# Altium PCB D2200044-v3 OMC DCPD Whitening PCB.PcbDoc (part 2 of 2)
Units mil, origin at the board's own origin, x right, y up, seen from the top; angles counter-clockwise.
Board outline 7000 x 5000 mil, 4 copper layers (Top Layer, Layer 1 (+V), Layer 2 (-V), Bottom Layer), stack 19.156 mil thick; 95 components, 56 nets, 274 pads, 56 vias.
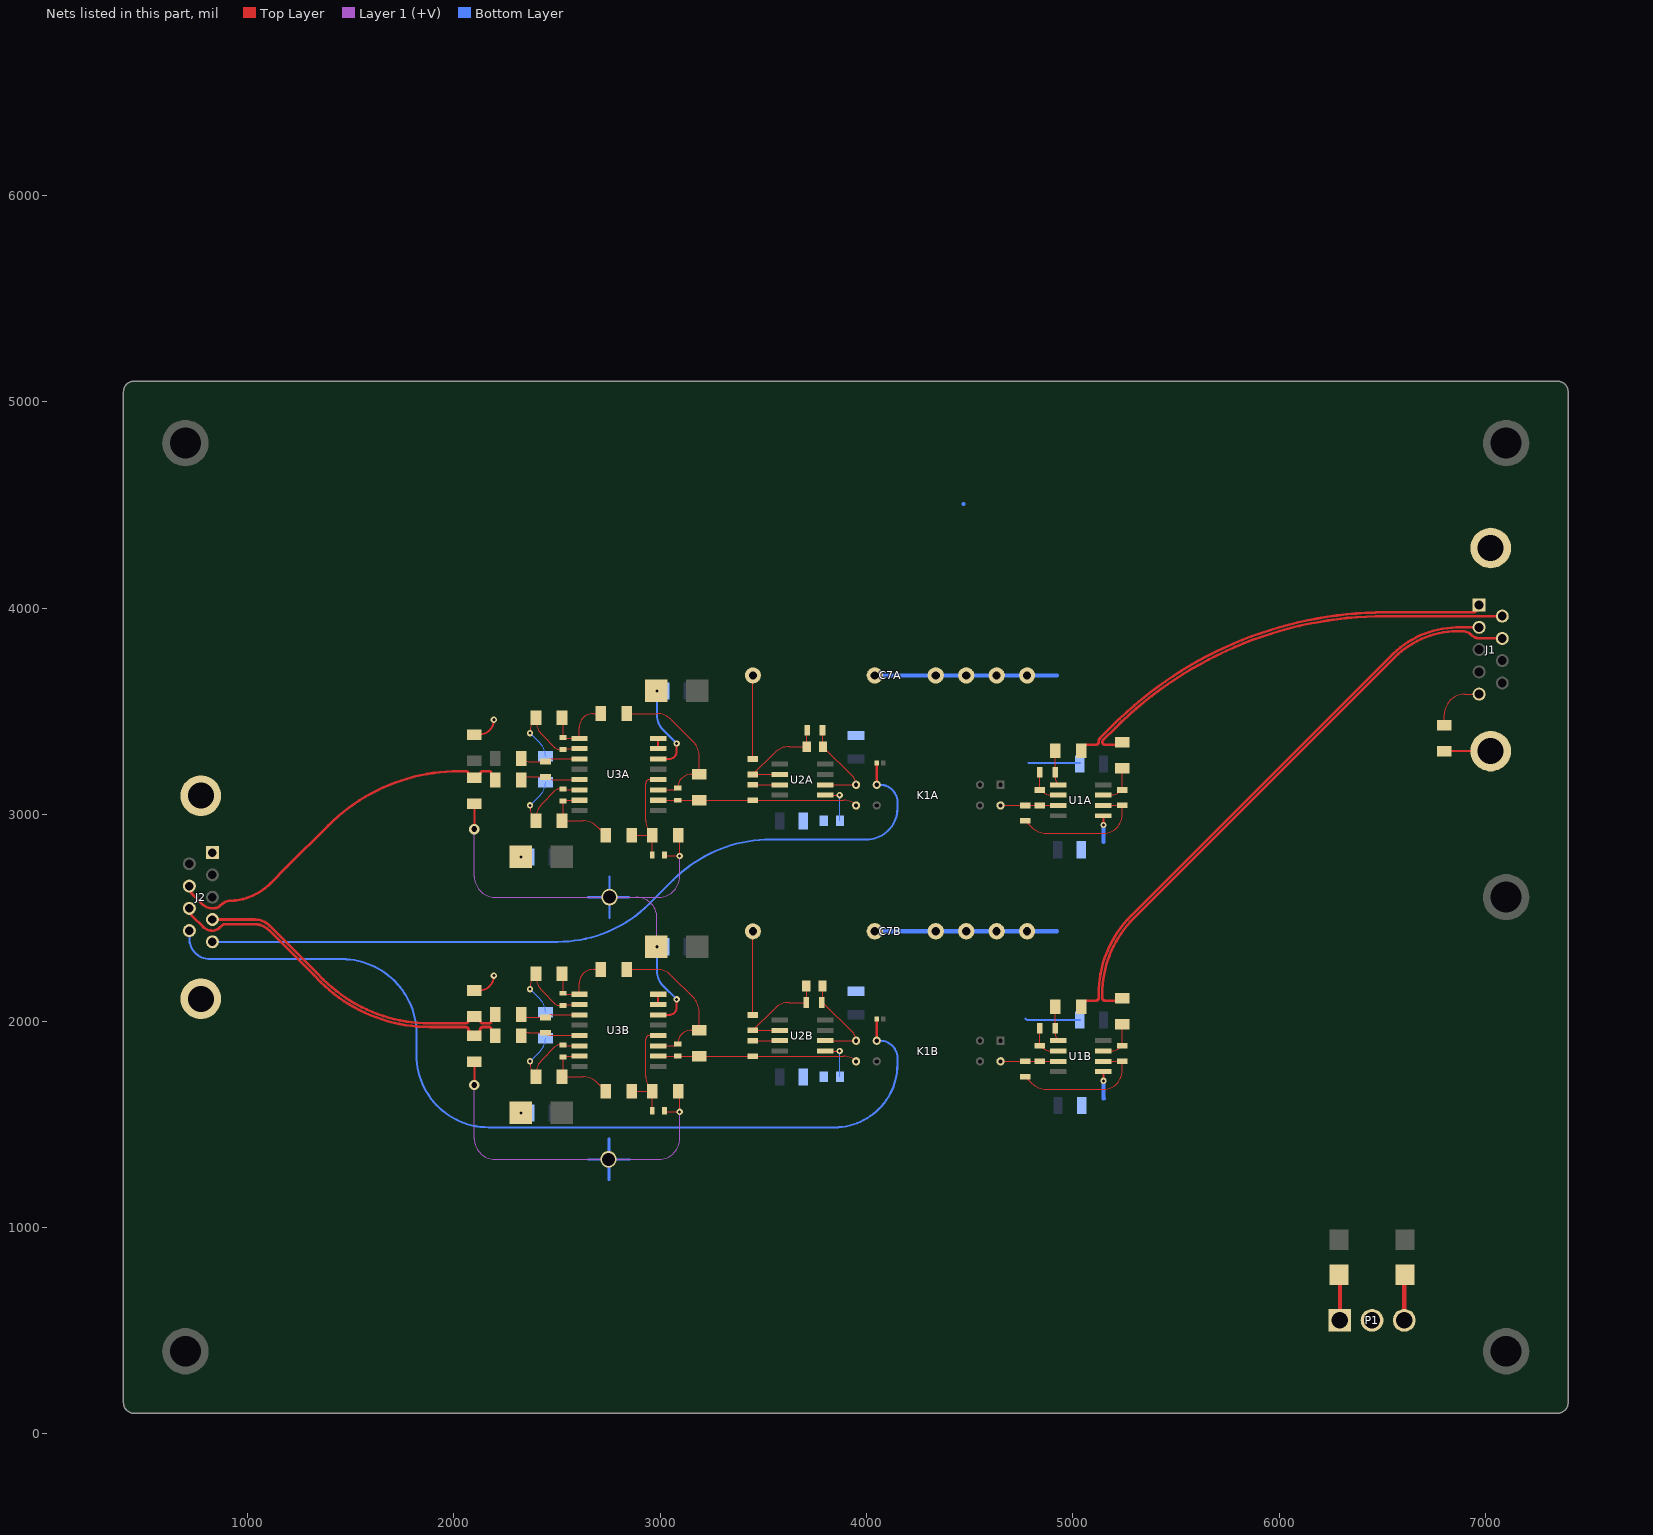
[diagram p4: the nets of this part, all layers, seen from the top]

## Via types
v1: diameter 31, hole 15, Top Layer to Bottom Layer, tented both sides, 52 vias
v2: diameter 50, hole 28, Top Layer to Bottom Layer, 2 vias
v3: diameter 31, hole 15, Top Layer to Bottom Layer, 2 vias

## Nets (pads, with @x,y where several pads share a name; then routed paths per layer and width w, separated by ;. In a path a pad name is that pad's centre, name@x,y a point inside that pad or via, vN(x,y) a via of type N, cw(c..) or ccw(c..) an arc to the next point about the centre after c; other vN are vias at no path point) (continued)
"DCPD In A_p": J2.7 R11A.1 R15A.1 | length 1833.9
  Top Layer w12.64: J2.7@719,2654 ccw(c779.36,2654) 736.68,2611.32 781.49,2566.51 ccw(c831,2616.01) 831,2546 834.79,2546 ccw(c834.79,2597.21) 870.99,2560.99 873.91,2563.91 cw(c920,2517.82) 910.17,2582.25 cw(c911.97,2569.74) 911.77,2582.38 ccw(c908.08,2870.33) 928.78,2583.1 ; 950.08,2585.44 cw(c908.08,2870.33) 928.79,2583.1 ; R15A.1@2202.01,3168 2188.57,3181.43 cw(c2202.66,3195.52) 2182.74,3195.52 2182.74,3198.54 ccw(c2170.1,3198.54) 2179.04,3207.48 ccw(c2170.1,3198.54) 2170.1,3211.18 2141.75,3211.18 ccw(c2141.75,3198.54) 2132.81,3207.48 2131.41,3206.07 ccw(c2136.97,3200.52) 2129.11,3200.52 cw(c2121.25,3200.52) 2126.81,3194.96 2116.8,3184.95 cw(c2100,3201.75) R11A.1@2100,3177.99 cw(c2100,3201.75) 2083.2,3184.95 2073.19,3194.96 cw(c2078.75,3200.52) 2070.89,3200.52 ccw(c2063.03,3200.52) 2068.59,3206.08 ccw(c2056.27,3193.76) 2056.27,3211.18 2028.84,3211.18 ccw(c2028.84,2311.49) 1392.95,2947.95 1193.45,2748.45 1111.68,2666.68 cw(c908.08,2870.33) 928.78,2583.1
"DCPD In B_n": J2.4 R17B.1 R21B.2 | length 1599.8
  Top Layer w12.64: J2.4@831,2492 1036.53,2492 cw(c1036.53,2392) 1107.24,2462.71 1335.35,2234.6 ; 1335.39,2234.56 1367.52,2202.43 1367.64,2202.31 ccw(c1883.57,2718.99) 1883.19,1988.82 2056.27,1988.82 ccw(c2056.27,2006.24) 2068.59,1993.92 ccw(c2063.03,1999.48) 2070.89,1999.48 cw(c2078.75,1999.48) 2073.19,2005.04 2083.2,2015.05 cw(c2100,1998.25) R21B.2@2100,2022.01 cw(c2100,1998.25) 2116.8,2015.05 2126.81,2005.04 cw(c2121.25,1999.48) 2129.11,1999.48 ccw(c2136.97,1999.48) 2131.41,1993.92 2132.81,1992.52 ccw(c2141.75,2001.46) 2141.75,1988.82 2170.1,1988.82 ccw(c2170.1,2001.46) 2179.04,1992.52 ccw(c2170.1,2001.46) 2182.74,2001.46 2182.74,2004.48 cw(c2202.66,2004.48) 2188.57,2018.57 R17B.1@2202.01,2032
"DCPD In B_p": J2.8 R11B.1 R15B.1 | length 1771.8
  Top Layer w12.64: J2.8@719,2546 ccw(c775.09,2546) 735.43,2506.34 784.51,2457.26 ccw(c831,2503.75) 831,2438 ccw(c831,2487.82) 866.23,2452.59 873.91,2460.27 cw(c896.74,2437.44) 896.74,2469.73 1033.85,2469.73 cw(c1033.85,2369.73) 1104.56,2440.44 1322.82,2222.18 1322.91,2222.09 1354.72,2190.28 ; 1354.73,2190.27 ccw(c1883.57,2718.99) 1883.24,1971.18 1883.69,1971.18 2056.27,1971.18 cw(c2056.27,1953.76) 2068.59,1966.08 cw(c2063.03,1960.52) 2070.89,1960.52 ccw(c2078.75,1960.52) 2073.19,1954.96 2083.2,1944.95 ccw(c2100,1961.75) 2100,1937.99 ccw(c2100,1961.75) 2116.8,1944.95 2126.81,1954.96 ccw(c2121.25,1960.52) 2129.11,1960.52 cw(c2136.97,1960.52) 2131.41,1966.07 2132.81,1967.48 cw(c2141.75,1958.54) 2141.75,1971.18 2170.1,1971.18 cw(c2170.1,1958.54) 2179.04,1967.48 cw(c2170.1,1958.54) 2182.74,1958.54 2182.74,1955.52 ccw(c2202.66,1955.52) 2188.57,1941.43 R15B.1@2202.01,1928
GND: C1A.2 C1B.2 C2A.2 C2B.2 C3A.2 C3B.2 C4A.2 C4B.2 C5A.2 C5B.2 C7A.2 C7B.2 C9A.2 C9B.2 C12A.2 C12B.2 C14A.2 C14B.2 C15A.2 C15B.2 C16A.1 C16B.1 J1.10 J1.11 J2.1 J2.10 J2.11 P1.2 R1.1 R11A.2 R11B.2 R14A.2 R14B.2 R21A.1 R21B.1 TP1A.1 TP1B.1 U1A.5 U1B.5 U3A.14 U3B.14 | length 8999.4
  Top Layer w6: C9B.2@3021.06,1565 3026.06,1560 3085,1560 v1@3090,1565 ; C9A.2@3021.06,2805 3026.06,2800 v1@3085,2800 ; R14B.2@3087.99,1660 3095,1652.99 3095,1570 v1@3090,1565 ; R14A.2@3087.99,2900 3095,2892.99 v1@3095,2810 ; v1(3095,1560) v1@3090,1565
  Top Layer w10: v2(2100,1690) R11B.2@2100,1802.02 ; R21B.1@2100,2147.99 2122.99,2147.99 ccw(c2122.99,2220) v1(2195,2220) ; v2(2100,2930) R11A.2@2100,3052.01 ; R21A.1@2100,3387.99 2122.99,3387.99 ccw(c2122.99,3460) v1(2195,3460) ; U3B.14@2990.94,2030 3045,2030 ccw(c3045,2065) 3080,2065 v1(3080,2105) ; U3A.14@2990.94,3270 3045,3270 ccw(c3045,3305) 3080,3305 v1(3080,3345) ; v1(5148.58,1710) U1B.5@5148.58,1754.8 ; v1(5148.58,2950) U1A.5@5148.58,2994.8 ; R1.1@6800,3308 J1.10@7025,3308
  Layer 1 (+V) w6: v2(2100,1690) 2100,1430 ccw(c2200,1430) 2200,1330 2995,1330 ccw(c2995,1430) 3095,1430 v1(3095,1560) ; v2(2100,2930) 2100,2700 ccw(c2200,2700) 2200,2600 2885,2600 ; v1(2985,2360) 2985,2500 ccw(c2885,2500) 2885,2600 ; v1(3095,2800) 3095,2700 cw(c2995,2700) 2995,2600 2885,2600
  Bottom Layer w10: 2650,1330 TP1B.1@2750,1330 ; 2650,2600 2850,2600 ; 2655,1330 TP1B.1@2755,1330 ; 2750,1230 TP1B.1@2750,1330 ; 2750,1430 TP1B.1@2750,1330 ; 2755,1230 TP1B.1@2755,1330 ; 2755,1430 TP1B.1@2755,1330 ; 2755,2500 TP1A.1@2755,2600 2755,2700 ; 2850,1330 TP1B.1@2750,1330 ; 2855,1330 TP1B.1@2755,1330 ; C15B.2@3022.91,2360 v1(2985,2360) 2985,2241.42 ccw(c3085,2241.42) 3014.29,2170.71 v1(3080,2105) ; C15A.2@3022.91,3600 v1(2985,3600) 2985,3481.42 ccw(c3085,3481.42) 3014.29,3410.71 v1(3080,3345) ; 4770,2011.2 ccw(c4784.97,2026.17) 4784.97,2005 C1B.2@5034.41,2005 ; 4784.97,3250 C1A.2@5034.41,3250
  Bottom Layer w20: C7B.2@4040.55,2435 4924,2435 ; C7A.2@4040.55,3675 C7A.2@4335.83,3675 C7A.2@4483.46,3675 C7A.2@4631.1,3675 C7A.2@4778.74,3675 4924,3675 ; 4470.2,4505 4471,4505 ; v1(5148.58,1710) 5148.58,1628.42 ccw(c5153.42,1628.42) 5150,1625 ; 5148.58,2868.42 v1(5148.58,2950)
  other v1: 2325.49,1555 2325.49,2795
NetC4A_1: C4A.1 U2A.5 | length 195
  Top Layer w5: U2A.5@3800,3094.8 v1(3870,3094.8)
  Bottom Layer w5: C4A.1@3870,2969.8 v1(3870,3094.8)
NetC4B_1: C4B.1 U2B.5 | length 195
  Top Layer w5: U2B.5@3800,1854.8 v1(3870,1854.8)
  Bottom Layer w5: C4B.1@3870,1729.8 v1(3870,1854.8)
NetC6A_1: C6A.1 R9A.1 R10A.2 U2A.2 | length 522.8
  Top Layer w5: U2A.2@3580,3194.8 R10A.2@3450,3194.8 3555.71,3300.51 cw(c3626.42,3229.8) 3626.42,3329.8 R9A.1@3710.63,3329.8 3710.63,3405.05 cw(c3717.35,3405.05) C6A.1@3712.6,3409.8
NetC6A_2: C6A.2 K1A.4 R9A.2 U2A.6 | length 479.5
  Top Layer w5: C6A.2@3787.4,3409.8 cw(c3782.65,3405.05) 3789.37,3405.05 R9A.2@3789.37,3329.8 3932.77,3186.41 cw(c3891.17,3144.8) K1A.4@3950,3144.8 U2A.6@3800,3144.8
NetC6B_1: C6B.1 R9B.1 R10B.2 U2B.2 | length 522.8
  Top Layer w5: U2B.2@3580,1954.8 R10B.2@3450,1954.8 3555.71,2060.51 cw(c3626.42,1989.8) 3626.42,2089.8 3710.63,2089.8 3710.63,2165.05 cw(c3717.35,2165.05) R9B.1@3712.6,2169.8
NetC6B_2: C6B.2 K1B.4 R9B.2 U2B.6 | length 479.5
  Top Layer w5: R9B.2@3787.4,2169.8 cw(c3782.65,2165.05) 3789.37,2165.05 3789.37,2089.8 3932.77,1946.41 cw(c3891.17,1904.8) K1B.4@3950,1904.8 U2B.6@3800,1904.8
NetC7A_1: C7A.1 R10A.1 | length 401.5
  Top Layer w5: R10A.1@3450,3273.54 C7A.1@3450,3675
NetC7B_1: C7B.1 R10B.1 | length 401.5
  Top Layer w5: R10B.1@3450,2033.54 C7B.1@3450,2435
NetC8A_1: C8A.1 R12A.1 R16A.2 U3A.6 | length 523.2
  Top Layer w6: v1(2370,3045) 2370,3040.05 ccw(c2469.07,3040.05) R12A.1@2399.02,2970 2399.02,2982.59 cw(c2499.02,2982.59) 2428.31,3053.31 2490,3115 cw(c2513,3092) 2513,3124.53 C8A.1@2530,3124.53 ccw(c2540.93,3135.46) 2540.93,3120 U3A.6@2609.06,3120
  Bottom Layer w6: v1(2370,3045) 2418.83,3093.83 ccw(c2355.66,3157.01) R16A.2@2445,3157.01
NetC8A_2: C8A.2 R12A.2 R13A.1 U3A.7 | length 413.8
  Top Layer w6: U3A.7@2609.06,3070 2540.93,3070 ccw(c2540.93,3054.54) C8A.2@2530,3065.47 2530,2982.07 cw(c2512.93,2982.07) R12A.2@2525,2970 2625.59,2970 cw(c2625.59,2870) 2696.3,2940.71 R13A.1@2737.01,2900
NetC8B_1: C8B.1 R12B.1 R16B.2 U3B.6 | length 523.2
  Top Layer w6: v1(2370,1805) 2370,1800.05 ccw(c2469.07,1800.05) R12B.1@2399.02,1730 2399.02,1742.59 cw(c2499.02,1742.59) 2428.31,1813.31 2490,1875 cw(c2513,1852) 2513,1884.53 C8B.1@2530,1884.53 ccw(c2540.93,1895.46) 2540.93,1880 U3B.6@2609.06,1880
  Bottom Layer w6: v1(2370,1805) 2418.83,1853.83 ccw(c2355.66,1917.01) R16B.2@2445,1917.01
NetC8B_2: C8B.2 R12B.2 R13B.1 U3B.7 | length 413.8
  Top Layer w6: U3B.7@2609.06,1830 2540.93,1830 ccw(c2540.93,1814.54) C8B.2@2530,1825.47 2530,1742.07 cw(c2512.93,1742.07) R12B.2@2525,1730 2625.59,1730 cw(c2625.59,1630) 2696.3,1700.71 R13B.1@2737.01,1660
NetC9A_1: C9A.1 R13A.2 R14A.1 U3A.12 | length 525.7
  Top Layer w6: R13A.2@2862.99,2900 R14A.1@2962.01,2900 ; C9A.1@2962.01,2805 R14A.1@2962.01,2900 ; U3A.12@2990.94,3170 2949.08,3170 ccw(c2949.08,3150.92) 2930,3150.92 2930,2973.43 ccw(c3030,2973.43) 2959.29,2902.72 R14A.1@2962.01,2900
NetC9B_1: C9B.1 R13B.2 R14B.1 U3B.12 | length 525.7
  Top Layer w6: R13B.2@2862.99,1660 R14B.1@2962.01,1660 ; C9B.1@2962.01,1565 R14B.1@2962.01,1660 ; U3B.12@2990.94,1930 2949.08,1930 ccw(c2949.08,1910.92) 2930,1910.92 2930,1733.43 ccw(c3030,1733.43) 2959.29,1662.72 R14B.1@2962.01,1660
NetC10A_1: C10A.1 R16A.1 R18A.1 U3A.2 | length 523.2
  Top Layer w5: v1(2370,3395) 2370,3399.95 cw(c2469.07,3399.95) R18A.1@2399.02,3470
  Top Layer w6: R18A.1@2399.02,3470 2399.02,3457.41 ccw(c2499.02,3457.41) 2428.31,3386.69 2490,3325 ccw(c2513,3348) 2513,3315.47 C10A.1@2530,3315.47 cw(c2540.93,3304.54) 2540.93,3320 U3A.2@2609.06,3320
  Bottom Layer w5: v1(2370,3395) 2418.83,3346.17 cw(c2355.66,3282.99) R16A.1@2445,3282.99
NetC10A_2: C10A.2 R18A.2 R19A.1 U3A.1 | length 396.3
  Top Layer w6: R18A.2@2525,3470 cw(c2512.93,3457.93) 2530,3457.93 C10A.2@2530,3374.53 ccw(c2540.93,3385.46) 2540.93,3370 U3A.1@2609.06,3370 2609.06,3423.13 cw(c2675.92,3423.13) 2675.92,3490 R19A.1@2737.01,3490
NetC10B_1: C10B.1 R16B.1 R18B.1 U3B.2 | length 523.2
  Top Layer w5: v1(2370,2155) 2370,2159.95 cw(c2469.07,2159.95) R18B.1@2399.02,2230
  Top Layer w6: R18B.1@2399.02,2230 2399.02,2217.41 ccw(c2499.02,2217.41) 2428.31,2146.69 2490,2085 ccw(c2513,2108) 2513,2075.47 C10B.1@2530,2075.47 cw(c2540.93,2064.54) 2540.93,2080 U3B.2@2609.06,2080
  Bottom Layer w5: v1(2370,2155) 2418.83,2106.17 cw(c2355.66,2042.99) R16B.1@2445,2042.99
NetC10B_2: C10B.2 R18B.2 R19B.1 U3B.1 | length 396.3
  Top Layer w6: R18B.2@2525,2230 cw(c2512.93,2217.93) 2530,2217.93 C10B.2@2530,2134.53 ccw(c2540.93,2145.46) 2540.93,2130 U3B.1@2609.06,2130 2609.06,2183.13 cw(c2675.92,2183.13) 2675.92,2250 R19B.1@2737.01,2250
NetC11A_1: C11A.1 R17A.2 U3A.3 | length 288.3
  Top Layer w6: R17A.2@2327.99,3272 ccw(c2363.24,3307.24) 2363.24,3257.4 C11A.1@2445,3257.4 cw(c2475.42,3226.99) 2475.42,3270 U3A.3@2609.06,3270
NetC11A_2: C11A.2 R15A.2 U3A.5 | length 288.3
  Top Layer w6: R15A.2@2327.99,3168 cw(c2363.24,3132.76) 2363.24,3182.6 C11A.2@2445,3182.6 ccw(c2475.42,3213.01) 2475.42,3170 U3A.5@2609.06,3170
NetC11B_1: C11B.1 R17B.2 U3B.3 | length 288.3
  Top Layer w6: R17B.2@2327.99,2032 ccw(c2363.24,2067.24) 2363.24,2017.4 C11B.1@2445,2017.4 cw(c2475.42,1986.99) 2475.42,2030 U3B.3@2609.06,2030
NetC11B_2: C11B.2 R15B.2 U3B.5 | length 288.3
  Top Layer w6: R15B.2@2327.99,1928 cw(c2363.24,1892.76) 2363.24,1942.6 C11B.2@2445,1942.6 ccw(c2475.42,1973.01) 2475.42,1930 U3B.5@2609.06,1930
NetC13A_1: C13A.1 R19A.2 R20A.1 U3A.11 | length 755.4
  Top Layer w6: R19A.2@2862.99,3490 2983.58,3490 cw(c2983.58,3390) 3054.29,3460.71 3160.71,3354.29 cw(c3090,3283.58) 3190,3283.58 R20A.1@3190,3195.98 3151.93,3195.98 ccw(c3151.93,3129.06) C13A.1@3085,3129.06 cw(c3063.14,3150.92) 3063.14,3120 U3A.11@2990.94,3120
NetC13A_2: C13A.2 K1A.5 R8A.1 R20A.2 U3A.10 | length 965.8
  Top Layer w5: U3A.10@2990.94,3070 C13A.2@3085,3070 R20A.2@3190,3070 R8A.1@3450,3070 3889.17,3070 cw(c3889.17,2983.97) K1A.5@3950,3044.8
NetC13B_1: C13B.1 R19B.2 R20B.1 U3B.11 | length 755.4
  Top Layer w6: R19B.2@2862.99,2250 2983.58,2250 cw(c2983.58,2150) 3054.29,2220.71 3160.71,2114.29 cw(c3090,2043.58) 3190,2043.58 R20B.1@3190,1955.98 3151.93,1955.98 ccw(c3151.93,1889.06) C13B.1@3085,1889.06 cw(c3063.14,1910.92) 3063.14,1880 U3B.11@2990.94,1880
NetC13B_2: C13B.2 K1B.5 R8B.1 R20B.2 U3B.10 | length 989.2
  Top Layer w5: R20B.2@3190,1830 R8B.1@3450,1830 3889.17,1830 cw(c3889.17,1743.97) K1B.5@3950,1804.8
  Top Layer w6: U3B.10@2990.94,1830 C13B.2@3085,1830 R20B.2@3190,1830 R20B.2@3189.76,1816.44 ; R20B.2@3189.75,1816.4 ccw(c3195.75,1816.33) 3189.75,1816.33 3189.76,1813.91 3191.43,1812.17 ccw(c3195.75,1816.33) 3191.6,1812 3193.27,1810.4 R20B.2@3195.58,1810.33
NetD1_1: D1.1 P1.1 | length 221.4
  Top Layer w20: D1.1@6290,770.35 cw(c6280.34,760.7) 6294,760.7 P1.1@6294,550
NetD2_2: D2.2 P1.3 | length 221.4
  Top Layer w20: P1.3@6606,550 6606,760.7 cw(c6619.66,760.7) D2.2@6610,770.35
NetJ1_5: J1.5 R1.2 | length 276.1
  Top Layer w6: R1.2@6800,3433.98 6800,3484 cw(c6900,3484) 6900,3584 J1.5@6969,3584
NetK1A_8: K1A.8 R3A.1 R6A.1 U1A.3 | length 278.6
  Top Layer w5: K1A.8@4650,3044.8 R6A.1@4770,3044.8 R3A.1@4840,3044.8 U1A.3@4928.58,3044.8
NetK1B_8: K1B.8 R3B.1 R6B.1 U1B.3 | length 278.6
  Top Layer w5: K1B.8@4650,1804.8 R6B.1@4770,1804.8 R3B.1@4840,1804.8 U1B.3@4928.58,1804.8
NetR2A_1: R2A.1 R3A.2 U1A.2 | length 180.6
  Top Layer w5: R2A.1@4840,3205 R3A.2@4840,3119.61 ccw(c4899.88,3179.49) 4899.88,3094.8 U1A.2@4928.58,3094.8
NetR2A_2: R2A.2 R4A.1 U1A.1 | length 169
  Top Layer w5: R4A.1@4915,3310 4915,3205.2 R2A.2@4914.8,3205 4914.8,3178.07 ccw(c4961.85,3178.07) U1A.1@4928.58,3144.8
NetR2B_1: R2B.1 R3B.2 U1B.2 | length 180.6
  Top Layer w5: R2B.1@4840,1965 R3B.2@4840,1879.61 ccw(c4899.88,1939.49) 4899.88,1854.8 U1B.2@4928.58,1854.8
NetR2B_2: R2B.2 R4B.1 U1B.1 | length 169
  Top Layer w5: R4B.1@4915,2070 4915,1965.2 R2B.2@4914.8,1965 4914.8,1938.07 ccw(c4961.85,1938.07) U1B.1@4928.58,1904.8
NetR5A_1: R5A.1 R6A.2 U1A.6 | length 677.8
  Top Layer w5: R6A.2@4770,2970 4800.71,2939.29 ccw(c4871.42,3010) 4871.42,2910 5148.58,2910 ccw(c5148.58,3001.42) 5240,3001.42 R5A.1@5240,3045 U1A.6@5148.78,3045
  Top Layer w10: U1A.6@5148.58,3044.8 U1A.6@5148.78,3045
NetR5A_2: R5A.2 R7A.1 U1A.7 | length 202.9
  Top Layer w5: U1A.7@5148.58,3094.8 5179.64,3094.8 ccw(c5179.64,3180.16) R5A.2@5240,3119.8 ; R5A.2@5240.2,3120 R7A.1@5240.2,3224.8
NetR5B_1: R5B.1 R6B.2 U1B.6 | length 677.8
  Top Layer w5: R6B.2@4770,1730 4800.71,1699.29 ccw(c4871.42,1770) 4871.42,1670 5148.58,1670 ccw(c5148.58,1761.42) 5240,1761.42 R5B.1@5240,1805 U1B.6@5148.78,1805
  Top Layer w10: U1B.6@5148.58,1804.8 U1B.6@5148.78,1805
NetR5B_2: R5B.2 R7B.1 U1B.7 | length 202.9
  Top Layer w5: U1B.7@5148.58,1854.8 5179.64,1854.8 ccw(c5179.64,1940.16) R5B.2@5240,1879.8 ; R5B.2@5240.2,1880 R7B.1@5240.2,1984.8
NetR8A_2: R8A.2 U2A.3 | length 130
  Top Layer w5: R8A.2@3450,3144.8 U2A.3@3580,3144.8
NetR8B_2: R8B.2 U2B.3 | length 130
  Top Layer w5: R8B.2@3450,1904.8 U2B.3@3580,1904.8
NetU3A_15: U3A.15 U3A.16 | length 50
  Top Layer w10: U3A.15@2990.94,3320 U3A.16@2990.94,3370
NetU3B_15: U3B.15 U3B.16 | length 50
  Top Layer w10: U3B.15@2990.94,2080 U3B.16@2990.94,2130
"OMC A - DCPD A_n": J1.6 R7A.2 | length 2221.6
  Top Layer w12.64: R7A.2@5240.2,3350.79 cw(c5212.01,3378.97) 5212.01,3339.11 5155.56,3339.11 cw(c5155.56,3351.75) 5146.62,3342.81 cw(c5155.56,3351.75) 5142.92,3351.75 cw(c5155.56,3351.75) 5146.61,3360.69 5205.88,3419.95 cw(c6515.19,2110.83) 6515.19,3962.34 6515.26,3962.34 6559.45,3962.34 6559.79,3962 J1.6@7081,3962
"OMC A - DCPD A_p": J1.1 R4A.2 | length 2157.3
  Top Layer w12.64: R4A.2@5040.98,3310 cw(c5064.75,3310) 5047.94,3326.8 5050.62,3329.48 cw(c5073.88,3306.22) 5073.88,3339.11 5112.63,3339.11 ccw(c5112.63,3351.75) 5121.57,3342.81 ccw(c5112.63,3351.75) 5125.28,3351.75 5125.28,3355.41 cw(c5146.74,3355.41) 5131.56,3370.58 5193.4,3432.43 cw(c6515.19,2110.83) 6515.19,3979.98 6558.77,3979.98 6559.11,3980.32 6933.32,3980.32 ccw(c6933.32,4016) J1.1@6969,4016
"OMC A - DCPD B_n": J1.7 R7B.2 | length 2887.3
  Top Layer w12.64: R7B.2@5240.2,2110.79 cw(c5212.01,2138.97) 5212.01,2099.11 5155.56,2099.11 cw(c5155.56,2111.75) 5146.62,2102.81 cw(c5155.56,2111.75) 5142.92,2111.75 5142.92,2131.79 cw(c5659.9,2131.47) 5294.26,2496.95 6559.74,3762.43 cw(c6865.74,3455.84) 6863.33,3889 6888.96,3889 cw(c6888.96,3830.96) 6930,3872 ccw(c6973.46,3915.46) 6973.46,3854 J1.7@7081,3854
"OMC A - DCPD B_p": J1.2 R4B.2 | length 2792.9
  Top Layer w12.64: R4B.2@5040.98,2070 cw(c5064.75,2070) 5047.94,2086.8 cw(c5077.66,2057.08) 5077.66,2099.11 5112.63,2099.11 ccw(c5112.63,2111.75) 5121.57,2102.81 ccw(c5112.63,2111.75) 5125.28,2111.75 5125.28,2131.39 5125.28,2131.74 cw(c5659.9,2131.47) 5281.93,2509.57 6468.18,3695.82 6546.89,3774.54 cw(c6867.17,3454.68) 6552.45,3780.01 6553.65,3781.16 cw(c6867.36,3454.22) 6858.33,3907.23 6860,3907.26 6967.22,3907.26 ccw(c6967.22,3909.78) J1.2@6969,3908
Whitening-A: D3A.1 J2.5 K1A.3 | length 3838.6
  Top Layer w10: K1A.3@4050,3144.8 D3A.1@4050,3249.8
  Bottom Layer w10: J2.5@831,2384 2504.04,2384 ccw(c2504.09,3011.47) 2947.82,2567.82 3064.59,2684.59 cw(c3536.31,2212.94) 3536.31,2880 4000.24,2880 ccw(c4000.24,3029.76) 4150,3029.76 4150,3061.69 ccw(c4066.88,3061.69) 4066.88,3144.8 K1A.3@4050,3144.8
Whitening-B: D3B.1 J2.9 K1B.3 | length 4494.3
  Top Layer w10: K1B.3@4050,1904.8 D3B.1@4050,2009.8
  Bottom Layer w10: J2.9@719,2438 719,2400 ccw(c819,2400) 819,2300 1457.97,2300 cw(c1457.97,1937.97) 1820,1937.97 1820,1833.84 ccw(c2168.84,1833.84) 2168.84,1485 3000.1,1485 ; 3000.15,1485 3845.24,1485 ccw(c3845.24,1789.76) 4150,1789.76 4150,1821.69 ccw(c4066.88,1821.69) 4066.88,1904.8 K1B.3@4050,1904.8
pads on no net: J1.3 J1.4 J1.8 J1.9 J2.2 J2.6 K1A.2 K1A.6 K1A.7 K1B.2 K1B.6 K1B.7 MH1.1 MH2.1 MH3.1 MH4.1 MH5.1 U2A.1 U2A.8 U2B.1 U2B.8 U3A.8 U3A.9 U3B.8 U3B.9

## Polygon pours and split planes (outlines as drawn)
no net on Top Overlay "NONET_L-01_P-001" (solid): 5640,230 5640,1480 6015,1480 6015,230
+15 on Layer 1 (+V) "+15_L02_P000" (solid, remove dead copper, pour order 0): 450,5000 cw(c500,5000) 500,5050 7300,5050 cw(c7300.01,5000.01) 7350,5000 7350,200 cw(c7300.02,199.98) 7300,150 500,150 cw(c499.99,199.99) 450,200
-15 on Layer 2 (-V) "-15_L03_P001" (solid, remove dead copper, pour order 1): 450,5000 cw(c500,5000) 500,5050 7300,5050 cw(c7300.01,5000.01) 7350,5000 7350,200 cw(c7307.42,192.58) 7300,150 500,150 cw(c499.99,199.99) 450,200
GND on Bottom Layer "GND_L04_P002" (solid, remove dead copper, pour order 2): 450,5000 cw(c500,5000) 500,5050 7300,5050 cw(c7300.01,5000.01) 7350,5000 7350,200 cw(c7300.01,199.99) 7300,150 500,150 cw(c499.99,199.99) 450,200

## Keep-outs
Top Layer:
  lines w10: 6165,1310 cw(c6215,1310) 6215,1360 6365,1360 ; 6165,1310 ccw(c6165,1310) 6165,1310 ; 6165,1310 6165,1160 ccw(c6215,1160) 6215,1110 ; 6215,1110 ccw(c6215,1110) 6215,1110 ; 6215,1110 6365,1110 ccw(c6365,1160) 6415,1160 6415,1310 ccw(c6365,1310) 6365,1360 ; 6365,1360 ccw(c6365,1360) 6365,1360 ; 6365,1360 6365,1360 ; 6487,1310 cw(c6537,1310) 6537,1360 6687,1360 ; 6487,1310 ccw(c6487,1310) 6487,1310 ; 6487,1310 6487,1160 ccw(c6537,1160) 6537,1110 ; 6537,1110 ccw(c6537,1110) 6537,1110 ; 6537,1110 6687,1110 ccw(c6687,1160) 6737,1160 6737,1310 ccw(c6687,1310) 6687,1360 ; 6687,1360 ccw(c6687,1360) 6687,1360
Layer 1 (+V):
  lines w10: 6485,1160 ccw(c6535,1160) 6535,1110 6685,1110 ccw(c6685,1160) 6735,1160 6735,1310 ccw(c6685,1310) 6685,1360 6535,1360 ccw(c6535,1310) 6485,1310 6485,1160
Layer 2 (-V):
  lines w10: 6165,1160 ccw(c6215,1160) 6215,1110 6365,1110 ccw(c6365,1160) 6415,1160 6415,1310 ccw(c6365,1310) 6365,1360 6215,1360 ccw(c6215,1310) 6165,1310 6165,1160
Bottom Layer:
  lines w10: 6165,1160 ccw(c6215,1160) 6215,1110 6365,1110 ccw(c6365,1160) 6415,1160 6415,1310 ccw(c6365,1310) 6365,1360 6215,1360 ccw(c6215,1310) 6165,1310 6165,1160 ; 6485,1160 ccw(c6535,1160) 6535,1110 6685,1110 ccw(c6685,1160) 6735,1160 6735,1310 ccw(c6685,1310) 6685,1360 6535,1360 ccw(c6535,1310) 6485,1310 6485,1160
  lines w25: 4040.55,2435 4846.06,2435 ; 4040.55,3675 4846.06,3675
Keep-Out Layer:
  circle w10: c4040.55,2435 r50
  circle w10: c4335.83,2435 r50
  circle w10: c4483.46,2435 r50
  circle w10: c4631.1,2435 r50
  circle w10: c4778.74,2435 r50
  circle w10: c4778.74,3675 r50
  circle w10: c4631.1,3675 r50
  circle w10: c4483.46,3675 r50
  circle w10: c4335.83,3675 r50
  circle w10: c5148.58,3190 r30
  circle w10: c5148.58,1950 r30
  circle w10: c5148.58,1710 r30
  circle w10: c5148.58,2950 r30
  circle w10: c4040.55,3675 r50
  circle w10: c4928.58,2950 r50
  circle w10: c4650,3144.8 r50
  circle w10: c4928.58,1710 r50
  circle w10: c4650,1904.8 r50
  circle w10: c3510,3094.8 r30
  circle w10: c3870,3194.8 r30
  circle w10: c3870,1954.8 r30
  circle w10: c3510,1854.8 r30
  circle w10: c3080,3345 r35
  circle w10: c3080,3220 r35
  circle w10: c2530,3220 r35
  circle w10: c2530,1980 r35
  circle w10: c3080,1980 r35
  circle w10: c3080,2105 r35
  rectangle: 2645,2975 2965,3415
  rectangle: 2645,1735 2965,2175
  lines w5: 2053,1841 2147,1841 ; 2053,3076 2147,3076 ; 2915,1613 cw(c2915,1585) 2943,1585 ; 2915,2853 cw(c2915,2825) 2943,2825 ; 3065,1613 ccw(c3065,1588) 3040,1588 3040,1585 ; 3065,2853 ccw(c3065,2828) 3040,2828 3040,2825 ; 2943,1585 cw(c2948,1585) 2948,1590 3035,1590 cw(c3035,1585) 3040,1585 ; 2943,1585 2943,1545 ccw(c2948,1545) 2948,1540 3035,1540 ccw(c3035,1545) 3040,1545 3040,1585 ; 2943,2825 cw(c2948,2825) 2948,2830 3035,2830 cw(c3035,2825) 3040,2825 ; 2943,2825 2943,2785 ccw(c2948,2785) 2948,2780 3035,2780 ccw(c3035,2785) 3040,2785 3040,2825 ; 2505,1811 ccw(c2510,1811) 2510,1806 2550,1806 ccw(c2550,1811) 2555,1811 2555,1898 ccw(c2550,1898) 2550,1903 2510,1903 ccw(c2510,1898) 2505,1898 2505,1811 ; 2505,2062 ccw(c2510,2062) 2510,2057 2550,2057 ccw(c2550,2062) 2555,2062 2555,2149 ccw(c2550,2149) 2550,2154 2510,2154 ccw(c2510,2149) 2505,2149 2505,2062 ; 2505,3051 ccw(c2510,3051) 2510,3046 2550,3046 ccw(c2550,3051) 2555,3051 2555,3138 ccw(c2550,3138) 2550,3143 2510,3143 ccw(c2510,3138) 2505,3138 2505,3051 ; 2505,3302 ccw(c2510,3302) 2510,3297 2550,3297 ccw(c2550,3302) 2555,3302 2555,3389 ccw(c2550,3389) 2550,3394 2510,3394 ccw(c2510,3389) 2505,3389 2505,3302 ; 3060,1816 ccw(c3065,1816) 3065,1811 3105,1811 ccw(c3105,1816) 3110,1816 3110,1903 ccw(c3105,1903) 3105,1908 3065,1908 ccw(c3065,1903) 3060,1903 3060,1816 ; 3060,3056 ccw(c3065,3056) 3065,3051 3105,3051 ccw(c3105,3056) 3110,3056 3110,3143 ccw(c3105,3143) 3105,3148 3065,3148 ccw(c3065,3143) 3060,3143 3060,3056
  lines w10: 2044,1970 cw(c2044,1961) 2053,1961 ; 2044,1990 ccw(c2044,1999) 2053,1999 ; 2044,3210 cw(c2044,3201) 2053,3201 ; 2044,3230 ccw(c2044,3239) 2053,3239 ; 2147,1865 cw(c2163,1865) 2163,1881 2179,1881 ; 2147,2095 ccw(c2163,2095) 2163,2079 2179,2079 ; 2147,3105 cw(c2163,3105) 2163,3121 2179,3121 ; 2147,3335 ccw(c2163,3335) 2163,3319 2179,3319 ; 2530,1980 cw(c2457.57,1907.57) 2560,1907.57 2560,1682 ; 2530,3220 cw(c2457.57,3147.57) 2560,3147.57 2560,2922 ; 2960,1735 2960,1732 ccw(c2985,1732) 2985,1707 ; 2960,2975 2960,2972 ccw(c2985,2972) 2985,2947 ; 3080,1980 3080,1996.01 cw(c3174.14,1996.01) 3107.57,2062.57 3169.9,2124.9 ; 3080,2105 3020.36,2164.64 cw(c3105.71,2250) 2985,2250 2985,2260.8 ccw(c2983.3,2260.8) 2984.5,2262 ; 3080,3220 3080,3236.01 cw(c3174.14,3236.01) 3107.57,3302.57 3169.9,3364.9 ; 3080,3345 3020.36,3404.64 cw(c3105.71,3490) 2985,3490 2985,3500.8 ccw(c2983.3,3500.8) 2984.5,3502 ; 3124,1746 3057,1746 cw(c3057,1796) 3007,1796 3007,2175 ccw(c2985,2175) 2985,2197 2562,2197 ; 3124,2986 3057,2986 cw(c3057,3036) 3007,3036 3007,3415 ccw(c2985,3415) 2985,3437 2562,3437 ; 3825,2174.8 3825,2124.3 ccw(c3944.5,2124.3) 3860,2039.8 ccw(c3884.14,2063.95) 3884.14,2029.8 4626.27,2029.8 cw(c4626.27,1936.07) 4720,1936.07 4720,1754.8 ; 3825,2176 cw(c3875,2176) 3875,2226 4820,2226 ccw(c4820,2276) 4870,2276 4870,2601 ccw(c4820,2601) 4820,2651 3564.86,2651 ccw(c3564.86,2430.14) 3344,2430.14 3344,2319 ccw(c3442.98,2319) 3372.99,2249.01 3379.64,2242.36 cw(c3294.29,2157) 3415,2157 3415,2109.8 3415,1829.8 ccw(c3440,1829.8) 3440,1804.8 3755,1804.8 cw(c3755,1684.09) 3840.36,1769.45 3855,1754.8 ccw(c3939.5,1839.3) 3939.5,1719.8 4685,1719.8 ; 4720,1790 4720,1754.8 ; 4720,1860 ccw(c4750,1860) 4750,1830 4760,1830 4785,1830 ccw(c4785,1850) 4805,1850 4805,1950.15 cw(c5009.85,1950.15) 5009.85,2155 5265,2155 cw(c5265,2130) 5290,2130 5290,1813.64 cw(c5136.36,1813.64) 5136.36,1660 4814.8,1660 cw(c4814.8,1756.09) 4746.86,1688.15 4745,1690 4736.55,1698.45 ccw(c4685,1646.9) 4685,1719.8 ; 4720,3100 ccw(c4750,3100) 4750,3070 4760,3070 4785,3070 ccw(c4785,3090) 4805,3090 4805,3190.15 cw(c5009.85,3190.15) 5009.85,3395 5265,3395 cw(c5265,3370) 5290,3370 5290,3053.64 cw(c5136.36,3053.64) 5136.36,2900 4814.8,2900 cw(c4814.8,2996.09) 4746.86,2928.15 4745,2930 4736.55,2938.45 ccw(c4685,2886.9) 4685,2959.8 ; 2053,1961 cw(c2067,1961) 2067,1975 2133,1975 cw(c2133,1961) 2147,1961 2147,1789 cw(c2133,1789) 2133,1775 2067,1775 cw(c2067,1789) 2053,1789 2053,1961 ; 2053,1999 ccw(c2067,1999) 2067,1985 2133,1985 ccw(c2133,1999) 2147,1999 2147,2171 ccw(c2133,2171) 2133,2185 2067,2185 ccw(c2067,2171) 2053,2171 2053,1999 ; 2053,3201 cw(c2067,3201) 2067,3215 2133,3215 cw(c2133,3201) 2147,3201 2147,3029 cw(c2133,3029) 2133,3015 2067,3015 cw(c2067,3029) 2053,3029 2053,3201 ; 2053,3239 ccw(c2067,3239) 2067,3225 2133,3225 ccw(c2133,3239) 2147,3239 2147,3411 ccw(c2133,3411) 2133,3425 2067,3425 ccw(c2067,3411) 2053,3411 2053,3239 ; 2179,1881 cw(c2179,1895) 2165,1895 2165,1961 cw(c2179,1961) 2179,1975 2351,1975 cw(c2351,1961) 2365,1961 2365,1895 cw(c2351,1895) 2351,1881 ; 2179,1881 2351,1881 ; 2179,2079 ccw(c2179,2065) 2165,2065 2165,1999 ccw(c2179,1999) 2179,1985 2351,1985 ccw(c2351,1999) 2365,1999 2365,2065 ccw(c2351,2065) 2351,2079 ; 2179,2079 2351,2079 ; 2179,3121 cw(c2179,3135) 2165,3135 2165,3201 cw(c2179,3201) 2179,3215 2351,3215 cw(c2351,3201) 2365,3201 2365,3135 cw(c2351,3135) 2351,3121 ; 2179,3121 2351,3121 ; 2179,3319 ccw(c2179,3305) 2165,3305 2165,3239 ccw(c2179,3239) 2179,3225 2351,3225 ccw(c2351,3239) 2365,3239 2365,3305 ccw(c2351,3305) 2351,3319 ; 2179,3319 2351,3319 ; 2351,1881 cw(c2351,1870) 2362,1870 2362,1763 ; 2351,2079 ccw(c2351,2090) 2362,2090 2362,2197 ; 2351,3121 cw(c2351,3110) 2362,3110 2362,3003 ; 2351,3319 ccw(c2351,3330) 2362,3330 2362,3437 ; 2362,1763 cw(c2376,1763) 2376,1777 2548,1777 cw(c2548,1763) 2562,1763 2562,1697 cw(c2548,1697) 2548,1683 ; 2362,1763 2362,1697 ccw(c2376,1697) 2376,1683 2548,1683 ; 2362,2197 ccw(c2376,2197) 2376,2183 2548,2183 ccw(c2548,2197) 2562,2197 ; 2362,2197 2362,2263 cw(c2376,2263) 2376,2277 2548,2277 ; 2362,3003 cw(c2376,3003) 2376,3017 2548,3017 cw(c2548,3003) 2562,3003 2562,2937 cw(c2548,2937) 2548,2923 ; 2362,3003 2362,2937 ccw(c2376,2937) 2376,2923 2548,2923 ; 2362,3437 ccw(c2376,3437) 2376,3423 2548,3423 ccw(c2548,3437) 2562,3437 ; 2362,3437 2362,3503 cw(c2376,3503) 2376,3517 2548,3517 ; 2548,1683 cw(c2548,1612.99) 2597.51,1662.49 2611.64,1648.36 ccw(c2697,1733.71) 2697,1613 2714,1613 ; 2548,2277 cw(c2548,2263) 2562,2263 2562,2197 ; 2548,2277 2595.51,2277 ccw(c2595.51,2297.49) 2610,2283 cw(c2643.8,2249.2) 2643.8,2297 2689,2297 ; 2548,2923 cw(c2548,2852.99) 2597.51,2902.49 2611.64,2888.36 ccw(c2697,2973.71) 2697,2853 2714,2853 ; 2548,3517 cw(c2548,3503) 2562,3503 2562,3437 ; 2548,3517 2595.51,3517 ccw(c2595.51,3537.49) 2610,3523 cw(c2643.8,3489.2) 2643.8,3537 2689,3537 ; 2689,2297 ccw(c2689,2283) 2675,2283 2675,2217 ccw(c2689,2217) 2689,2203 2861,2203 ccw(c2861,2217) 2875,2217 2875,2283 ; 2689,2297 2861,2297 cw(c2861,2283) 2875,2283 ; 2689,3537 ccw(c2689,3523) 2675,3523 2675,3457 ccw(c2689,3457) 2689,3443 2861,3443 ccw(c2861,3457) 2875,3457 2875,3523 ; 2689,3537 2861,3537 cw(c2861,3523) 2875,3523 ; 2714,1613 cw(c2714,1627) 2700,1627 2700,1693 cw(c2714,1693) 2714,1707 2886,1707 cw(c2886,1693) 2900,1693 2900,1627 cw(c2886,1627) 2886,1613 ; 2714,1613 2886,1613 ; 2714,2853 cw(c2714,2867) 2700,2867 2700,2933 cw(c2714,2933) 2714,2947 2886,2947 cw(c2886,2933) 2900,2933 2900,2867 cw(c2886,2867) 2886,2853 ; 2714,2853 2886,2853 ; 2875,2283 ccw(c2896,2283) 2896,2262 2984.5,2262 ; 2875,3523 ccw(c2896,3523) 2896,3502 2984.5,3502 ; 2886,1613 2939,1613 ; 2886,2853 2939,2853 ; 2939,1613 cw(c2939,1627) 2925,1627 2925,1693 cw(c2939,1693) 2939,1707 3111,1707 cw(c3111,1693) 3125,1693 ; 2939,1613 3111,1613 ccw(c3111,1627) 3125,1627 3125,1693 ; 2939,2853 cw(c2939,2867) 2925,2867 2925,2933 cw(c2939,2933) 2939,2947 3111,2947 cw(c3111,2933) 3125,2933 ; 2939,2853 3111,2853 ccw(c3111,2867) 3125,2867 3125,2933 ; 2984.5,2262 cw(c2984.5,2142.5) 3069,2227 3164.64,2131.36 cw(c3079.29,2046) 3200,2046 3200,2010 ccw(c3217,2010) 3217,1993 3223,1993 ; 2984.5,3502 cw(c2984.5,3382.5) 3069,3467 3164.64,3371.36 cw(c3079.29,3286) 3200,3286 3200,3250 ccw(c3217,3250) 3217,3233 3223,3233 ; 3125,1693 3125,1761 cw(c3157,1761) 3157,1793 ; 3125,2933 3125,3001 cw(c3157,3001) 3157,3033 ; 3157,1793 cw(c3157,1807) 3143,1807 3143,1979 cw(c3157,1979) 3157,1993 3223,1993 ; 3157,1793 3223,1793 ccw(c3223,1807) 3237,1807 3237,1979 ccw(c3223,1979) 3223,1993 ; 3157,3033 cw(c3157,3047) 3143,3047 3143,3219 cw(c3157,3219) 3157,3233 3223,3233 ; 3157,3033 3223,3033 ccw(c3223,3047) 3237,3047 3237,3219 ccw(c3223,3219) 3223,3233 ; 4685,1719.8 ccw(c4685,1754.8) 4720,1754.8 ; 4685,2959.8 ccw(c4685,2994.8) 4720,2994.8 4720,3176.07 ccw(c4626.27,3176.07) 4626.27,3269.8 3884.14,3269.8 cw(c3884.14,3303.95) 3860,3279.8 cw(c3944.5,3364.3) 3825,3364.3 3825,3414.8 3825,3416 cw(c3875,3416) 3875,3466 4820,3466 ccw(c4820,3516) 4870,3516 4870,3841 ccw(c4820,3841) 4820,3891 3564.86,3891 ccw(c3564.86,3670.14) 3344,3670.14 3344,3559 ccw(c3442.98,3559) 3372.99,3489.01 3379.64,3482.36 cw(c3294.29,3397) 3415,3397 3415,3349.8 3415,3069.8 ccw(c3440,3069.8) 3440,3044.8 3755,3044.8 cw(c3755,2924.09) 3840.36,3009.45 3855,2994.8 ccw(c3939.5,3079.3) 3939.5,2959.8 4685,2959.8 ; 5000,1950.15 5000,2055 5180,2055 5180,1950.15 5000,1950.15 ; 5000,3190.15 5180,3190.15 5180,3295 5000,3295 5000,3190.15
  lines w20: 3870,1954.8 3870,2029.8 ; 3870,3194.8 3870,3272.87 ; 4650,1904.8 4650,2026.75 ; 4650,3144.8 4650,3266.75 ; 5035,2005 4815,2005 4917.57,2005 cw(c4917.57,1902.57) 4990,1975 ccw(c5050.36,2035.36) 5050.36,1950 5148.58,1950 ; 5035,3245 4815,3245 4917.57,3245 cw(c4917.57,3142.57) 4990,3215 ccw(c5050.36,3275.36) 5050.36,3190 5148.58,3190
  lines w40: 729.8,2549 ccw(c729.8,3160.28) 1162.04,2728.04 1225,2791 1394.99,2960.99 cw(c2020.3,2335.68) 2020.3,3220 2042,3220 ; 832,2434 849.8,2434 cw(c849.8,1776.84) 1314.48,2241.52 1356.69,2199.31 ccw(c1886.14,2728.76) 1886.14,1980 2035,1980 ; 3237,1829.8 3415,1829.8 ; 3237,3069.8 3415,3069.8

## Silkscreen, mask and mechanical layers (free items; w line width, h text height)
Top Overlay:
  drawing of 51 lines, arcs and shapes, not listed
  text "Disable" at 4161.5,3953.81 h100 r45
  text "Whitening" at 3369.92,3837.8 h100 r45
  text "GND" at 4477.03,3470 h60
  text "Differential Reciever" at 2289.95,3451.1 h100 r45
  text "Differential Driver" at 5096.95,3390.1 h100 r45
  text "To: Rear Panel" at 6684.98,3141.88 h100 r90
  text "Whitened Output" at 6483.32,3108.56 h100 r90
  text "DCPD A" at 1919.98,2846.11 h120 r90
  text "GND" at 2676.03,2695 h60
  text "GND" at 4477.03,2230 h60
  text "DCPD B" at 1909.98,1631.11 h120 r90
  text "From: Front Interface" at 1134.98,1608.65 h100 r90
  text "GND" at 2672.03,1425 h60
  text "+15V" at 6349.98,1390.07 h120 r90
  text "-15V" at 6669.98,1390.07 h120 r90
  text "OMC DCPD Whitening / D2200044-v3" at 5569.61,235 h100 r90
Mechanical 1:
  the board outline again, w5

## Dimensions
719.09,2600 to 260,4800 on Mechanical 1
7380,4800 to 7380,400 on Mechanical 1
7100,5060 to 700,5120 on Mechanical 1
7400,5100 to 400,5100 on Mechanical 1
7400,5100 to 7400,100 on Mechanical 1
